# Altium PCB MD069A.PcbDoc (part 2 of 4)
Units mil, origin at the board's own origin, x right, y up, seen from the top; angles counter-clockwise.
Board outline 4569 x 3239 mil, 4 copper layers (Top Layer, Signal Layer 1, Signal Layer 2, Bottom Layer), stack 61.2 mil thick; 187 components, 103 nets, 560 pads, 220 vias.
Unrouted connection lines stored in the file: 7.
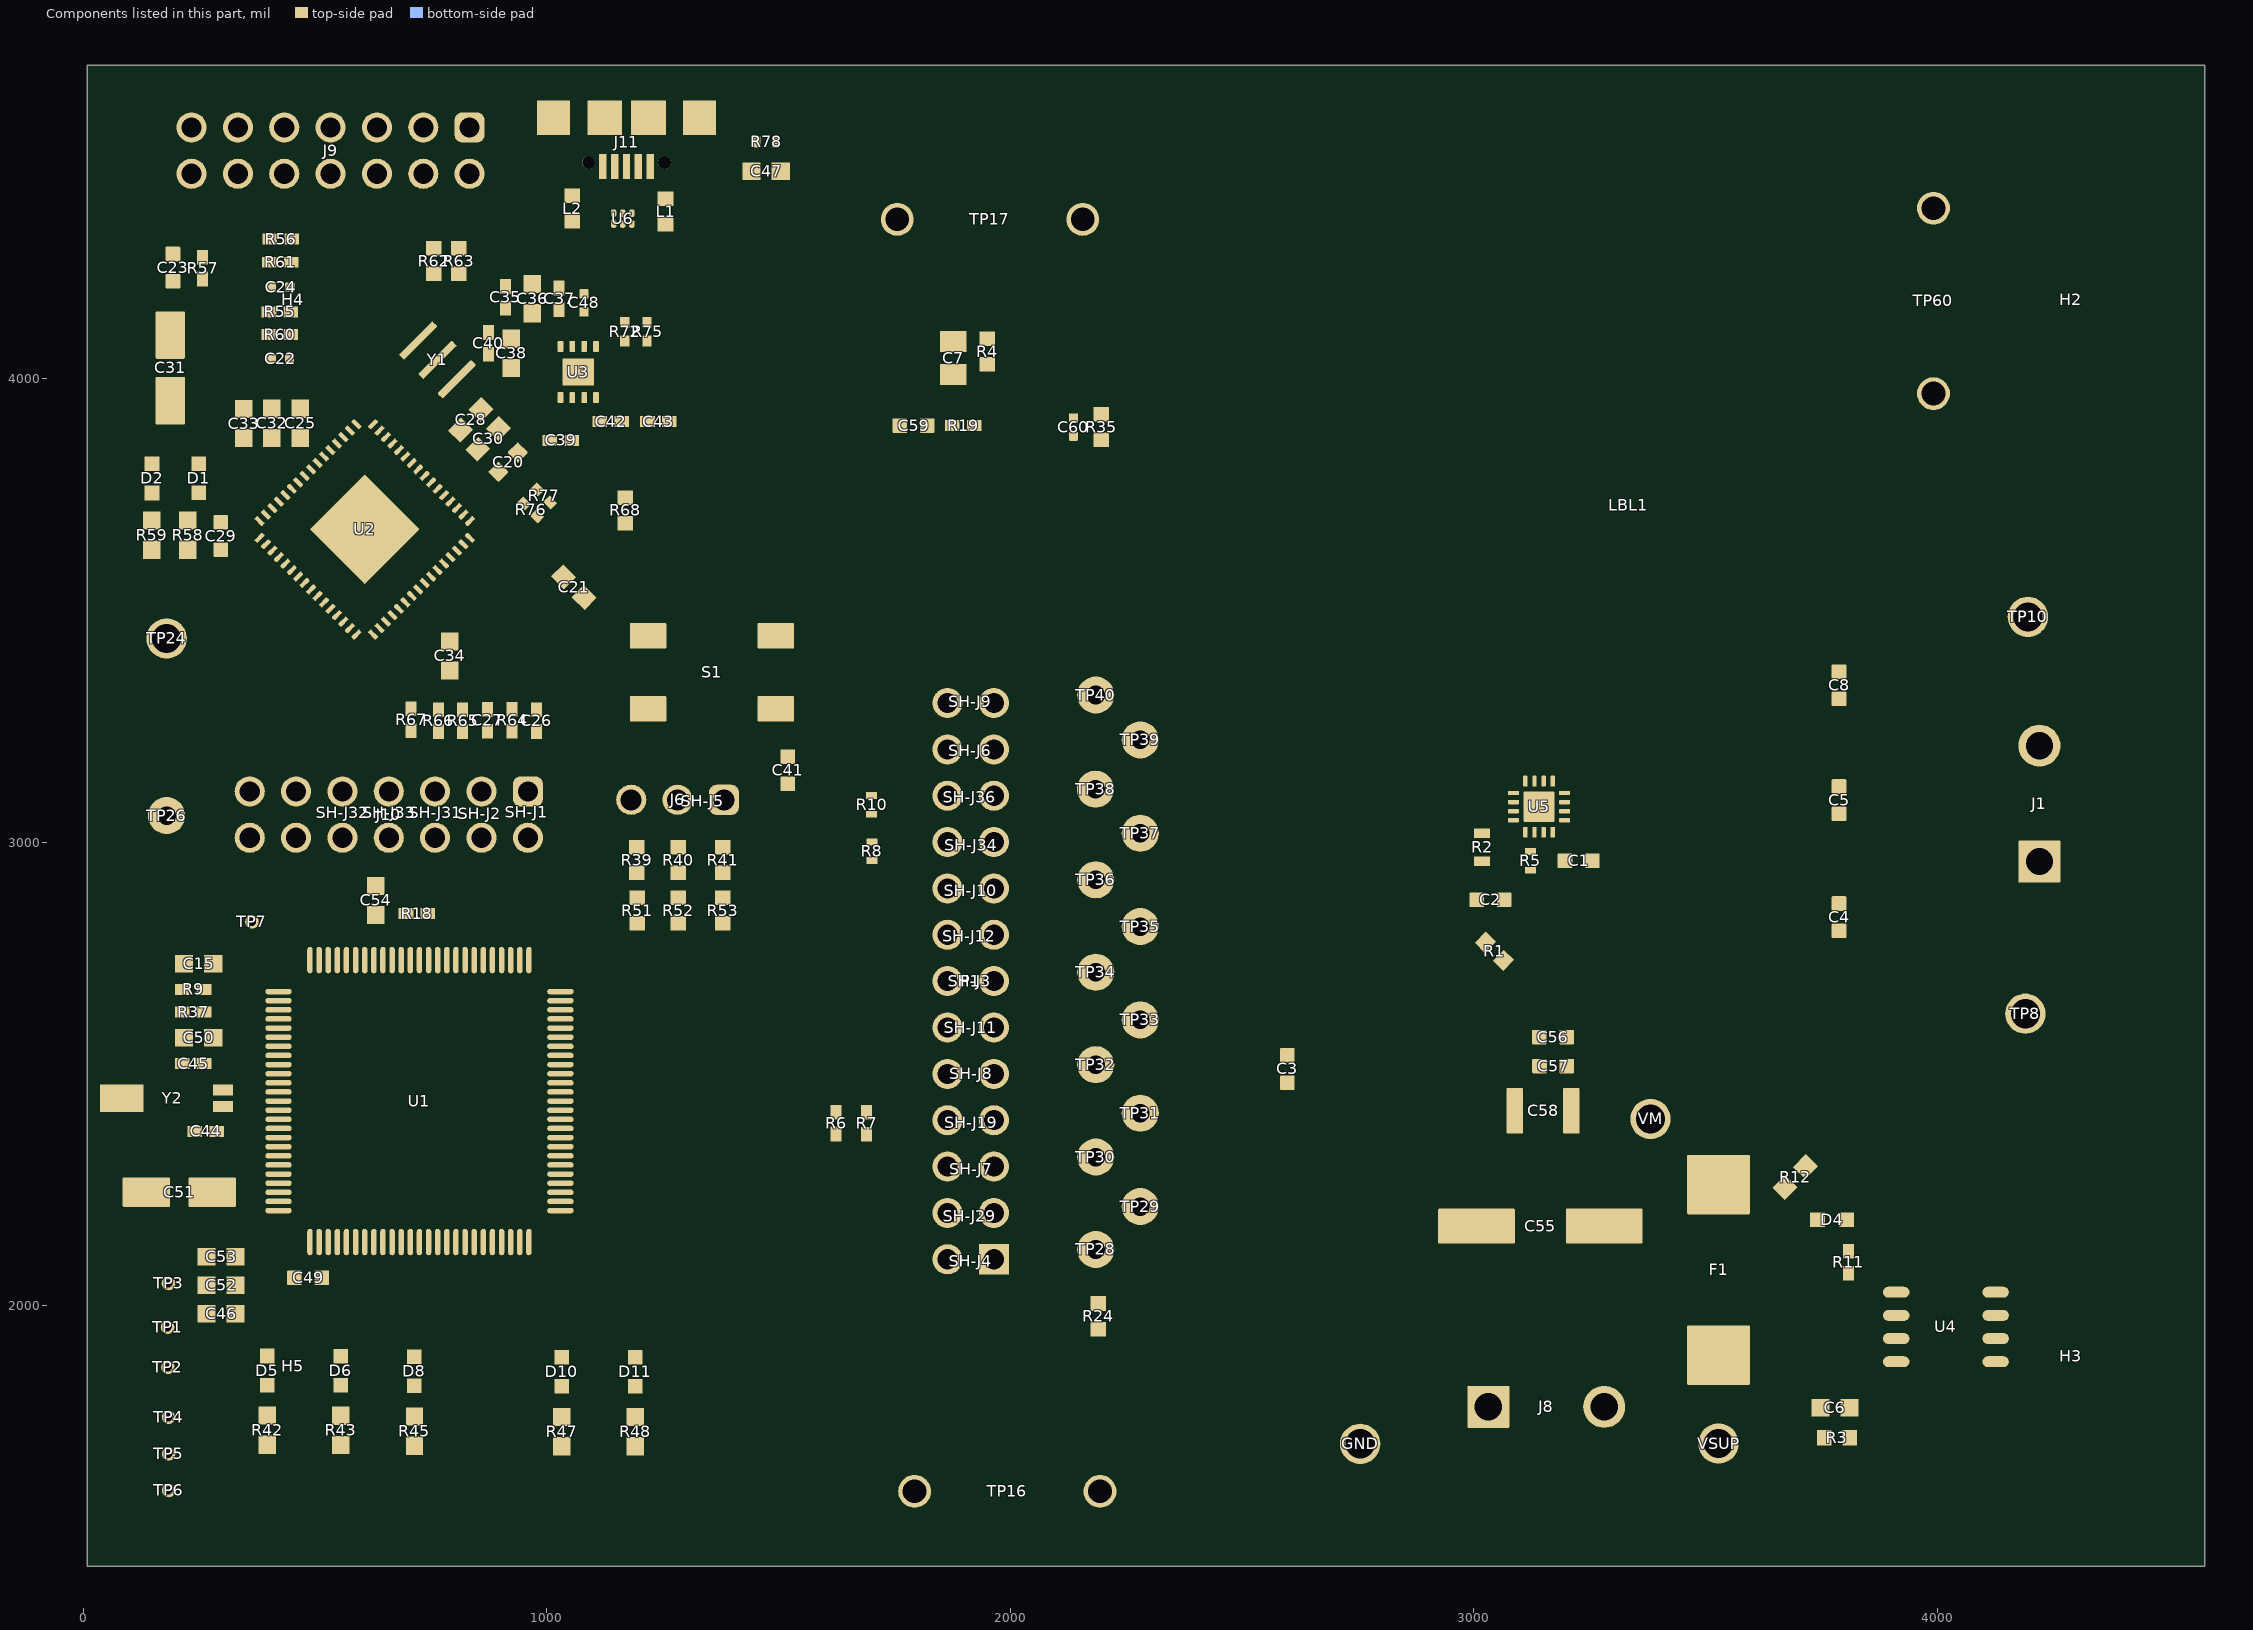
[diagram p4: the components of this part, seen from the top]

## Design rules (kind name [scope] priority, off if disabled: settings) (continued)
PolygonConnect PolygonConnect_4 [All vs IsNamedPolygon('TOP_LAYER_VM_P046')] p91: connectstyle=Direct reliefconductorwidth=10 reliefentries=4 polygonreliefangle="90 Angle" airgapwidth=10
PolygonConnect PolygonConnect_3 [All vs IsNamedPolygon('TOP_LAYER_GND_P036') Or  IsNamedPolygon('TOP_LAYER_OUT2_P040') Or  IsNamedPolygon('TOP_LAYER_OUT1_P038')] p92: connectstyle=Direct reliefconductorwidth=10 reliefentries=4 polygonreliefangle="90 Angle" airgapwidth=10
PolygonConnect PolygonConnect_2 [InNet('EZFET_VBUS') vs IsNamedPolygon('TOP_LAYER_EZFET_VBUS_P008')] p93: connectstyle=Direct reliefconductorwidth=10 reliefentries=4 polygonreliefangle="90 Angle" airgapwidth=10
PolygonConnect PolygonConnect_1 [InNetClass('Power-Net') vs IsNamedPolygon('TOP_LAYER_EZFET_USB_SHIELD_P201')] p94: connectstyle=Direct reliefconductorwidth=10 reliefentries=4 polygonreliefangle="90 Angle" airgapwidth=10
PolygonConnect [All] p95: connectstyle=Direct reliefconductorwidth=10 reliefentries=4 polygonreliefangle="90 Angle" airgapwidth=10
RoutingVias ThermalPadVias [IsVia and InAnyComponent] p1: holewidth=7.87 width=19.68 viastyle="Through Hole" minholewidth=7.87 minwidth=19.68 maxholewidth=12.99 maxwidth=23.62
RoutingVias [All] p2: holewidth=16 width=34 viastyle="Through Hole" minholewidth=7.87 minwidth=26 maxholewidth=40 maxwidth=65
SilkToBoardRegionClearance [Not ((IsComment or IsDesignator) And (Hide <> 'False')) and not InRegion(1000,500,4000,800)] p1:
SilkToSilkClearance SilkToSilkClearance_Pb-FreeLogo [(HasFootprint('Pb-Free_Overlay_Medium') OR HasFootprint('Pb-Free_Overlay_Small')) vs (HasFootprint('Pb-Free_Overlay_Medium') OR HasFootprint('Pb-Free_Overlay_Small'))] p1: silktosilkclearance=0
SilkToSilkClearance [All] p2: silktosilkclearance=3.94
SilkToSolderMaskClearance SilkToComponentPadClearance [(IsPad or IsFill or IsRegion) and InAnycomponent] p1: minsilkscreentomaskgap=5 clearancetoexposedcopper=TRUE
SilkToSolderMaskClearance "Silk to Solder Mask Opening" [All] p2: minsilkscreentomaskgap=3.94 clearancetoexposedcopper=FALSE
SolderMaskExpansion [All] p1: expansion=1.97 istentingtop=FALSE
UnRoutedNet [All] p1: checkbadconnections=TRUE
Width [All] p1: maxlimit=65 minlimit=4 preferedwidth=15 minimp=50.000000 maximp=50.000000 favimp=50.000000 checkconnectedcopper=TRUE
14 further rules are at their usual default settings.

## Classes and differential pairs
component class MD069A_Hardware: !PCB1 H2 H3 H4 H5 LBL1 Logo1 Logo2 Logo3 Logo4 LOGO5 ZZ1 ZZ2 ZZ3 ZZ4
component class MD069A: C1 C2 C3 C4 C5 C6 C7 C8 C15 C41 C44 C45 C46 C49 C50 C51 C52 C53 C54 C55 C56 C57 C58 C59 C60 D4 D5 D6 D8 D10 D11 F1 GND J1 J6 J8 P1 R1 R2 R3 R4 R5 R6 R7 R8 R9 R10 R11 R12 R18 R19 R24 R35 R37 R39 R40 R41 R42 R43 R45 R47 R48 R51 R52 R53 S1 SH-J1 SH-J2 SH-J3 SH-J4 SH-J5 SH-J6 SH-J7 SH-J8 SH-J9 SH-J10 SH-J11 SH-J12 SH-J19 SH-J36 TP1 TP2 TP3 TP4 TP5 TP6 TP7 TP8 TP10 TP16 TP17 TP24 TP26 TP28 TP29 TP30 TP31 TP32 TP33 TP34 TP35 TP36 TP37 TP38 TP39 TP40 TP60 U1 U4 U5 VM VSUP Y2
component class Shunt: SH-J1 SH-J2 SH-J3 SH-J4 SH-J5 SH-J6 SH-J7 SH-J8 SH-J9 SH-J10 SH-J11 SH-J12 SH-J19 SH-J29 SH-J31 SH-J32 SH-J33 SH-J34 SH-J36
net class Power-Net: EZFET_VBUS EZFET_VCC GND MCU_3V3
component class Header: J6 J9 J10
component class MD069A_ezFET: C20 C21 C22 C23 C24 C25 C26 C27 C28 C29 C30 C31 C32 C33 C34 C35 C36 C37 C38 C39 C40 C42 C43 C47 C48 D1 D2 J9 J10 J11 L1 L2 R55 R56 R57 R58 R59 R60 R61 R62 R63 R64 R65 R66 R67 R68 R72 R75 R76 R77 R78 SH-J29 SH-J31 SH-J32 SH-J33 SH-J34 U2 U3 U6 Y1
component class Logo: Logo2
component class AssemblyNote: ZZ1 ZZ2 ZZ3 ZZ4
component class Label: LBL1
differential pair USB_D: +USB_D_P -USB_D_N
differential pair EZFET_D: +EZFET_D_P -EZFET_D_N

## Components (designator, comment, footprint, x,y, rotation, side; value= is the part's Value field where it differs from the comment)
C1 "885012206120" FP-885012206120_0603-MFG 3225.89,2960.41 r180 top value=100nF
C2 "885012206120" FP-885012206120_0603-MFG 3035.54,2875.94 r0 top value=100nF
C3 "885012006085" FP-885012006085_0603-MFG 2597.56,2511.17 r90 top value=1nF
C4 "885012006085" FP-885012006085_0603-MFG 3787.61,2838.57 r90 top value=1nF
C5 "885012006085" FP-885012006085_0603-MFG 3787.61,3091.04 r270 top value=1nF
C6 "885012206095" 0603 3778.83,1780.3 r0 top value=0.1uF
C7 "885012107011" 0805_150 1876.75,4044.85 r270 top value=22uF
C8 "885012006085" FP-885012006085_0603-MFG 3787.61,3339.04 r270 top value=1nF
C15 "885012206095" 0603 248.63,2738.54 r180 top value=0.1uF
C20 "885012106012" FP-885012106012_0603-MFG 916.28,3820.21 r225 top value=4.7µF
C21 "885012206095" 0603 1058.3,3550.7 r315 top value=0.1uF
C22 "885012005058" FP-885012005058_0402-MFG 425.27,4043.12 r0 top value=33pF
C23 "885012006085" FP-885012006085_0603-MFG 193.39,4239.89 r90 top value=1nF
C24 "885012005058" FP-885012005058_0402-MFG 425.71,4197.93 r0 top value=33pF
C25 "885012206095" 0603 467.95,3904.1 r90 top value=0.1uF
C26 "885012005055" 0402 977.55,3262.77 r270 top value=10pF
C27 "885012005055" 0402 871.56,3263 r270 top value=10pF
C28 "885012206048" 0603 835.93,3911.48 r45 top value=0.22uF
C29 "885012106008" FP-885012106008_0603-MFG 296.85,3660.71 r270 top value=470nF
C30 "885012206048" 0603 873.13,3870.41 r45 top value=0.22uF
C31 "875105240001" FP-875105240001_SMT_CAP_4MM3_4MM3-MFG 187.54,4023.63 r270 top value=10µF
C32 "885012206095" 0603 406.51,3904.1 r90 top value=0.1uF
C33 "885012206095" 0603 346.36,3903.67 r90 top value=0.1uF
C34 "885012206095" 0603 790.72,3402.12 r90 top value=0.1uF
C35 "885012105012" 0402 910.39,4175.6 r90 top value=1uF
C36 "885012206095" 0603 968.11,4173.17 r90 top value=0.1uF
C37 "885012205031" 0402 1026.24,4172.43 r90 top value=0.01uF
C38 "885012106018" 0603 922.83,4055.06 r90 top value=2.2uF
C39 "885012205031" 0402 1029.71,3867.23 r0 top value=0.01uF
C40 "885012105012" 0402 873.88,4076.47 r90 top value=1uF
C41 "885012006085" FP-885012006085_0603-MFG 1519.79,3155.67 r270 top value=1nF
C42 "885012005055" 0402 1137.9,3907.66 r180 top value=10pF
C43 "885012005055" 0402 1240.69,3907.66 r0 top value=10pF
C44 "885012005055" 0402 263.9,2376.79 r0 top value=10pF
C45 "885012005055" 0402 236.65,2522.82 r180 top value=10pF
C46 "885012206095" 0603 297.02,1983.23 r0 top value=0.1uF
C47 "885012206048" 0603 1473,4448.03 r0 top value=0.22uF
C48 "885012205018" FP-885012205018_0402-MFG 1080,4164 r90 top value=100nF
C49 "885012106008" FP-885012106008_0603-MFG 484.94,2060.9 r0 top value=470nF
C50 "885012206095" 0603 248.63,2578.4 r180 top value=0.1uF
C51 "875105240001" FP-875105240001_SMT_CAP_4MM3_4MM3-MFG 206.98,2245.41 r0 top value=10µF
C52 "885012206095" 0603 297.02,2044.31 r180 top value=0.1uF
C53 "885012206095" 0603 297.02,2105.92 r180 top value=0.1uF
C54 "885012206095" 0603 630.92,2874.69 r270 top value=0.1uF
C55 "865060653010" WCAP-ASLL_800x1050 3143.27,2172.32 r180 top value=100uF
C56 "885012206120" FP-885012206120_0603-MFG 3170.41,2580.05 r0 top value=100nF
C57 "885012006085" FP-885012006085_0603-MFG 3170.93,2517.49 r0 top value=1nF
C58 "885012209069" FP-885012209069_1210-MFG 3149.12,2420.93 r0 top value=1µF
C59 "885012006085" FP-885012006085_0603-MFG 1791,3899 r0 top value=1nF
C60 "885012005080" FP-885012005080_0402-MFG 2136,3896 r270 top value=100pF
D1 "150060RS75000" WL-SMCW_RED 249.42,3785.56 r270 top value=Red
D2 "150060VS75000" WL-SMCW_GREEN 148.2,3785.34 r270 top value=Green
D4 "150060VS75000" WL-SMCW_GREEN 3772.65,2186.22 r180 top value=Green
D5 "150060VS75000" WL-SMCW_GREEN 396.79,1860.48 r90 top value=Green
D6 "150060VS75000" WL-SMCW_GREEN 555.36,1860 r90 top value=Green
D8 "150060VS75000" WL-SMCW_GREEN 714.26,1859 r90 top value=Green
D10 "150060YS75000" WL-SMCW_YELLOW 1032.04,1858 r90 top value=Yellow
D11 "150060SS75000" WL-SMCW_RED 1190.94,1858 r90 top value="Super Red"
F1 "0463030.ER" Fuse_0463 3527.57,2077.72 r90 top
GND "5011" Keystone5011 2754.6,1702.49 r270 top
H2 "SJ61A1" Bumpon_SJ61A1 4287,4171 r180 bottom
H3 "SJ61A1" Bumpon_SJ61A1 4287,1891.31 r180 bottom
H4 "SJ61A1" Bumpon_SJ61A1 452,4171 r180 bottom
H5 "SJ61A1" Bumpon_SJ61A1 452,1870 r180 bottom
J1 "691250610002" FP-691250610002_CONN_TERM_BLOCK2-MFG 4284.9,3071.9 r90 top
J6 "61300311121" WURTH_61300311121 1282,3091.91 r180 top
J8 "691250610002" FP-691250610002_CONN_TERM_BLOCK2-MFG 3144.18,1717.35 r0 top
J9 "61301421121" Wurth_61301421121 533.43,4492.4 r270 top
J10 "61301421121" Wurth_61301421121 659,3060.02 r270 top
J11 "629105136821" 629105136821 1171.82,4563.32 r180 top
L1 "742792621" 0603L 1255.92,4360.74 r270 top value="140 ohm"
L2 "742792621" 0603L 1054.9,4367.31 r270 top value="140 ohm"
LBL1 "THT-14-423-10" Label_650x200 3332.42,3727.31 r0 top
Logo1 "CE Mark" CE_Mark_5mm 2540.7,3556.79 r0 top
Logo2 "Texas Instruments" TI_Stacked_Overlay_Medium 3116.15,4366.68 r0 top
Logo3 "FCC disclaimer" FCC_disclaimer 1560.47,1632 r0 top
Logo4 "WEEE logo" WEEE_Minimum 2508.73,3972.39 r0 top
LOGO5 "CAUTION HOT SURFACE" IEC_HotSurface_Small 3521.09,3066.59 r0 top
P1 "61302621121" 61302621121 1914.3,2700.7 r90 top
R1 "RC0603JR-0710KL" 0603L 3043.95,2765.1 r315 top value=10k
R2 "ERJ-3EKF1501V" 0603S 3017.48,2989.55 r270 top value=1.50k
R3 "Resistor" 0603L 3783.18,1715.13 r180 top value=0
R4 "Resistor" 0603L 1950,4059 r90 top value=0
R5 "RC0402JR-070RL" 0402S 3121.71,2959.91 r90 top value=0
R6 "CRCW04022K21FKED" 0402 1624.16,2394.62 r90 top value=2.21k
R7 "CRCW04022K21FKED" 0402 1689.93,2394.36 r90 top value=2.21k
R8 "RC0402JR-070RL" 0402S 1701.01,2980.93 r90 top value=0
R9 "CRCW040210R0FKED" 0402 236.65,2683.03 r180 top value=10.0
R10 "RC0402JR-070RL" 0402S 1700.67,3080.69 r90 top value=0
R11 "CRCW0402680RJNED" 0402 3807.56,2094.38 r90 top value=680
R12 "RG1608P-3012-B-T5" 0603 3693.21,2278.11 r225 top value=30.1k
R18 "CRCW040247K0JNED" 0402 719.67,2846.49 r0 top value=47k
R19 "CRCW040247K0JNED" 0402 1898.54,3899.14 r0 top value=47k
R24 "RC0603JR-0710KL" 0603L 2189.37,1977.63 r90 top value=10k
R35 "CRCW06034K99FKEA" 0603L 2196,3896 r270 top value=4.99k
R37 "CRCW040210R0FKED" 0402 236.65,2633.71 r0 top value=10.0
R39 "RC0603JR-0710KL" 0603L 1194.18,2961.73 r270 top value=10k
R40 "RC0603JR-0710KL" 0603L 1283.18,2961.73 r270 top value=10k
R41 "RC0603JR-0710KL" 0603L 1379.34,2961.73 r270 top value=10k
R42 "RC0603JR-07560RL" 0603 396.5,1732.21 r90 top value=560
R43 "CRCW0603330RJNEA" 0603 555.4,1731.74 r90 top value=330
R45 "CRCW0603330RJNEA" 0603 714.29,1729.74 r90 top value=330
R47 "CRCW0603330RJNEA" 0603 1032.08,1728.74 r90 top value=330
R48 "CRCW0603330RJNEA" 0603 1190.97,1728.74 r90 top value=330
R51 "RC0603JR-0710KL" 0603L 1194.54,2852.73 r270 top value=10k
R52 "RC0603JR-0710KL" 0603L 1283.61,2852.73 r270 top value=10k
R53 "RC0603JR-0710KL" 0603L 1379.69,2852.73 r270 top value=10k
R55 "RC0402FR-07220KL" 0402 424.06,4144.57 r180 top value=220k
R56 "CRCW0402240KFKED" 0402 425.71,4301.28 r180 top value=240k
R57 "CRCW040247K0JNED" 0402 257.39,4239.11 r270 top value=47k
R58 "RC0603JR-07470RL" 0603 225.05,3662.98 r90 top value=470
R59 "RC0603JR-07560RL" 0603 147.47,3662.94 r90 top value=560
R60 "RC0402FR-07220KL" 0402 423.82,4095.42 r0 top value=220k
R61 "CRCW0402150KFKED" 0402 425.32,4251.56 r0 top value=150k
R62 "Resistor" 0603L 756.08,4254.24 r270 top value=0
R63 "Resistor" 0603L 809.84,4253.99 r270 top value=0
R64 "CRCW040210R0FKED" 0402 924.87,3263.29 r270 top value=10.0
R65 "CRCW040210R0FKED" 0402 818.39,3262.44 r270 top value=10.0
R66 "CRCW040210R0FKED" 0402 765.89,3262.8 r270 top value=10.0
R67 "CRCW040210R0FKED" 0402 706.9,3264.38 r270 top value=10.0
R68 "Resistor" 0603L 1169.5,3716.36 r90 top value=0
R72 "CRCW040227R0JNED" 0402L 1167.94,4101.57 r270 top value=27
R75 "CRCW040227R0JNED" 0402L 1216.37,4101.57 r270 top value=27
R76 "CRCW04021K40FKED" 0402L 964.89,3717.33 r315 top value=1.40k
R77 "CRCW04021M00JNED" 0402L 993.35,3747.35 r135 top value=1.0Meg
R78 "CRCW040233K0JNED" 0402S 1473,4511 r180 top value=33k
S1 "430481025816" FP-430481025816_SMT_SW_6MM2_6MM2-MFG 1356,3367 r180 top
SH-J1 "60900213421" Wurth_60900213421 956.09,3064.66 r90 top
SH-J2 "60900213421" Wurth_60900213421 855.52,3062.26 r90 top
SH-J3 "60900213421" Wurth_60900213421 1912.17,2700.94 r180 top
SH-J4 "60900213421" Wurth_60900213421 1914.34,2096.07 r180 top
SH-J5 "60900213421" Wurth_60900213421 1336.05,3088.57 r180 top
SH-J6 "60900213421" Wurth_60900213421 1913.63,3197.29 r180 top
SH-J7 "60900213421" Wurth_60900213421 1915.5,2294.66 r180 top
SH-J8 "60900213421" Wurth_60900213421 1915.5,2500.47 r180 top
SH-J9 "60900213421" Wurth_60900213421 1912.93,3303.11 r180 top
SH-J10 "60900213421" Wurth_60900213421 1914.83,2895.42 r180 top
SH-J11 "60900213421" Wurth_60900213421 1913.95,2600.07 r180 top
SH-J12 "60900213421" Wurth_60900213421 1911.43,2797.73 r180 top
SH-J19 "60900213421" Wurth_60900213421 1915.5,2395.23 r180 top
SH-J29 "60900213421" Wurth_60900213421 1912.26,2193.54 r180 top
SH-J31 "60900213421" Wurth_60900213421 760,3064 r90 top
SH-J32 "60900213421" Wurth_60900213421 560,3064 r90 top
SH-J33 "60900213421" Wurth_60900213421 660,3064 r90 top
SH-J34 "60900213421" Wurth_60900213421 1915.02,2993.99 r180 top
SH-J36 "60900213421" Wurth_60900213421 1912.23,3097.03 r180 top
TP1 "TP_H0.45P0.75" TP_H045P075 181.74,1954.01 r0 top
TP2 "TP_H0.45P0.75" TP_H045P075 182.41,1867.43 r90 top
TP3 "TP_H0.45P0.75" TP_H045P075 183.74,2048.59 r0 top
TP4 "TP_H0.45P0.75" TP_H045P075 184,1760 r0 top
TP5 "TP_H0.45P0.75" TP_H045P075 184,1681 r0 top
TP6 "TP_H0.45P0.75" TP_H045P075 184,1602 r90 top
TP7 "TP_H0.45P0.75" TP_H045P075 363.7,2828.57 r90 top
TP8 "5012" Keystone5012 4189.57,2630.36 r90 top
TP10 "5012" Keystone5012 4195.05,3486.48 r90 top
TP16 "Jumper_2p" Harwin_D3082-05 1993.22,1599.99 r180 top
TP17 "Jumper_2p" Harwin_D3082-05 1955.92,4344.03 r0 top
TP24 "5011" Keystone5011 179.7,3440 r0 top
TP26 "5003" Keystone5003 179.7,3057.87 r0 top
TP28 "5002" Keystone5002 2184.18,2121.77 r0 top
TP29 "5002" Keystone5002 2280.18,2214.47 r0 top
TP30 "5002" Keystone5002 2184.18,2321.14 r0 top
TP31 "5002" Keystone5002 2280.18,2415.79 r0 top
TP32 "5002" Keystone5002 2184.18,2520.5 r0 top
TP33 "5002" Keystone5002 2280.18,2617.1 r180 top
TP34 "5002" Keystone5002 2184.18,2719.86 r180 top
TP35 "5002" Keystone5002 2280.18,2818.42 r180 top
TP36 "5002" Keystone5002 2184.18,2919.23 r180 top
TP37 "5002" Keystone5002 2280.18,3019.73 r180 top
TP38 "5002" Keystone5002 2183.57,3114.89 r180 top
TP39 "5002" Keystone5002 2280.18,3221.05 r180 top
TP40 "5002" Keystone5002 2184.18,3317.95 r180 top
TP60 "Jumper_2p" Harwin_D3082-05 3991.31,4168.2 r270 top
U1 "MSP430F5338IPZ" PZT0100A_N 725.16,2442 r0 top
U2 "MSP430F5528IRGCT" RGC0064B 606.92,3675.21 r315 top
U3 "TPS73533DRBR" DRB0008A 1067.69,4014.77 r90 top
U4 "LM9036M-3.3/NOPB" D0008A_N 4018.2,1954.66 r180 top
U5 "DRV8214RTER" RTE0016C-MFG 3140.46,3077.05 r90 top
U6 "TPD2E001DRYR" DRY0006A 1163.72,4345.58 r90 top
VM "5010" Keystone5010 3380.98,2403.35 r270 top
VSUP "5010" Keystone5010 3527.57,1703.13 r270 top
Y1 "CSTNR4M00GH5L000R0" MuRata_CSTNR 764.02,4040.94 r135 top
Y2 "MS3V-T1R 32.768KHZ +/-20PPM 12.5PF" XTAL_MS3V-T1R 192,2448 r180 top
ZZ1 "These assemblies are ESD sensitive, ESD precautions shall be observed." AssemblyNote 1277,977 r0 top
ZZ2 "These assemblies must be clean and free from flux and all contaminants. Use of no clean flux is not acceptable." AssemblyNote 1268,1071 r0 top
ZZ3 "These assemblies must comply with workmanship standards IPC-A-610 Class 2, unless otherwise specified." AssemblyNote 1268,874 r0 top
ZZ4 "This Assembly Note is for PCB labels only" AssemblyNoteLabel 1263,775 r0 top

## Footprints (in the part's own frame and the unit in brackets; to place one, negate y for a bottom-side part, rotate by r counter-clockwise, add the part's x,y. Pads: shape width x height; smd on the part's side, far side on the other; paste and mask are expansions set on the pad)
0402 [mm] "0402 from SM-752 data"
  rect 0.8x0.6 smd: 1(-0.6,0) 2(0.6,0)
  silkscreen extent -1.22,-0.52 1.22,0.52, body extent -0.55,-0.3 0.55,0.3, height 0.6
0402L [mm] "0402 from SM-752 data"
  rect 0.6x0.5 smd: 1(-0.5,0) 2(0.5,0)
  body extent -0.55,-0.3 0.55,0.3, height 0.6
0402S [mil] "Based on C0402S footprint from PADS legacy"
  rect 15x24 smd: 1(-20,0) 2(20,0)
  body extent -22,-12 22,12, height 24
0603 [mm] "0603 from SM-752 data"
  rect 1x0.95 smd: 1(-0.8,0) 2(0.8,0)
  silkscreen extent -1.52,-0.69 1.52,0.69, body extent -0.87,-0.47 0.87,0.47, height 1
0603L [mm] "0603 from SM-752 data"
  rect 0.8x0.85 smd: 1(-0.7,0) 2(0.7,0)
  silkscreen extent -0.07,-0.33 0.07,0.33, body extent -0.87,-0.47 0.87,0.47, height 1
0603S [mil]
  rect 20x35 smd: 1(-30,0) 2(30,0)
  body extent -34,-19 34,19, height 39
0805_150 [mm] "0805 / 1.5 mm height"
  rect 1.15x1.45 smd: 1(-0.9,0) 2(0.9,0)
  silkscreen extent -0.1,-0.8 0.1,0.8, body extent -1.1,-0.72 1.1,0.72, height 1.5
61302621121 [mm] "Pin Header, pitch 2.54 mm, THT, Vertical, dual row, 26p"
  rect 1.65x1.65 hole 1.1: 1(-15.24,-1.27)
  round 1.65 hole 1.1: 2(-15.24,1.27) 3(-12.7,-1.27) 4(-12.7,1.27) 5(-10.16,-1.27) 6(-10.16,1.27) 7(-7.62,-1.27) 8(-7.62,1.27) 9(-5.08,-1.27) 10(-5.08,1.27) 11(-2.54,-1.27) 12(-2.54,1.27) 13(0,-1.27) 14(0,1.27) 15(2.54,-1.27) 16(2.54,1.27) 17(5.08,-1.27) 18(5.08,1.27) 19(7.62,-1.27) 20(7.62,1.27) 21(10.16,-1.27) 22(10.16,1.27) 23(12.7,-1.27) 24(12.7,1.27) 25(15.24,-1.27) 26(15.24,1.27)
  silkscreen extent -16.66,-2.62 16.66,2.62, body extent -16.51,-2.54 16.51,2.54, height 8.59
629105136821 [mm] "Micro USB 2.0 SMT Type B Horizontal 5 Contacts"
  rect 0.4x1.35 smd: 1(-1.3,2.675) 2(-0.65,2.675) 3(0,2.675) 4(0.65,2.675) 5(1.3,2.675)
  round 0.7 hole 0.7 unplated: MH1(-2.075,2.45) MH2(2.075,2.45)
  rect 1.8x1.9 smd: Shell(-4,0) Shell(4,0)
  rect 1.9x1.9 smd: Shell(-1.2,0) Shell(1.2,0)
  silkscreen extent -3.7,1.25 3.7,2.85, body extent -4,-2.73 4,3.17, height 2.69
AssemblyNote [mil] "Assembly Note"
AssemblyNoteLabel [mil] "Assembly Note for PCB Labels"
Bumpon_SJ61A1 [mil] "3M Cylindrical Bumpon black"
  round 1 on Mech4: 0(0,0)
  silkscreen extent -156,-156 156,156, body extent -156,-156 156,156, height 201
CE_Mark_5mm [mil] "Minimum text height for CE Mark"
  silkscreen extent -138,-98 138,98
D0008A_N [mm] "SOIC, 8-Leads, Body 4.9x3.9mm, Pitch 1.27mm, IPC Medium Density"
  oval 1.45x0.6 smd: 1(-2.725,1.905) 2(-2.725,0.635) 3(-2.725,-0.635) 4(-2.725,-1.905) 5(2.725,-1.905) 6(2.725,-0.635) 7(2.725,0.635) 8(2.725,1.905)
  silkscreen extent -3.3,-2.5 0.9,2.5, body extent -3,-2.45 3,2.45, height 1.63
DRB0008A [mm] "VSON-8"
  rrect32% 0.6x0.31 smd: 1(-1.4,0.975) 2(-1.4,0.325) 3(-1.4,-0.325) 4(-1.4,-0.975) 5(1.4,-0.975) 6(1.4,-0.325) 7(1.4,0.325) 8(1.4,0.975)
  rrect7% 1.5x1.75 smd paste-0.75: 9(0,0)
  Top Layer region: -0.7,-0.875 -0.49,-0.875 -0.471,-0.879 -0.455,-0.89 -0.444,-0.906 -0.44,-0.925 -0.44,-0.925 -0.44,-1.65 -0.436,-1.669 -0.425,-1.685 -0.409,-1.696 -0.39,-1.7 -0.39,-1.7 -0.26,-1.7 -0.241,-1.696 -0.225,-1.685 -0.214,-1.669 -0.21,-1.65 -0.21,-1.65 -0.21,-0.925 -0.206,-0.906 -0.195,-0.89 -0.179,-0.879 -0.16,-0.875 -0.16,-0.875 0.16,-0.875 0.179,-0.879 0.195,-0.89 0.206,-0.906 0.21,-0.925 0.21,-0.925 0.21,-1.65 0.21,-1.65 0.214,-1.669 0.225,-1.685 0.241,-1.696 0.26,-1.7 0.26,-1.7 0.39,-1.7 0.409,-1.696 0.425,-1.685 0.436,-1.669 0.44,-1.65 0.44,-1.65 0.44,-0.925 0.444,-0.906 0.455,-0.89 0.471,-0.879 0.49,-0.875 0.49,-0.875 0.7,-0.875 0.719,-0.871 0.735,-0.86 0.746,-0.844 0.75,-0.825 0.75,-0.825 0.75,0.825 0.746,0.844 0.735,0.86 0.719,0.871 0.7,0.875 0.7,0.875 0.49,0.875 0.471,0.879 0.455,0.89 0.444,0.906 0.44,0.925 0.44,0.925 0.44,1.65 0.436,1.669 0.425,1.685 0.409,1.696 0.39,1.7 0.39,1.7 0.26,1.7 0.241,1.696 0.225,1.685 0.214,1.669 0.21,1.65 0.21,1.65 0.21,1.65 0.21,0.925 0.206,0.906 0.195,0.89 0.179,0.879 0.16,0.875 0.16,0.875 -0.16,0.875 -0.179,0.879 -0.195,0.89 -0.206,0.906 -0.21,0.925 -0.21,0.925 -0.21,1.65 -0.214,1.669 -0.225,1.685 -0.241,1.696 -0.26,1.7 -0.26,1.7 -0.39,1.7 -0.409,1.696 -0.425,1.685 -0.436,1.669 -0.44,1.65 -0.44,1.65 -0.44,0.925 -0.444,0.906 -0.455,0.89 -0.471,0.879 -0.49,0.875 -0.49,0.875 -0.7,0.875 -0.719,0.871 -0.735,0.86 -0.746,0.844 -0.75,0.825 -0.75,0.825 -0.75,-0.825 -0.746,-0.844 -0.735,-0.86 -0.719,-0.871 -0.7,-0.875
  silkscreen extent -1.73,-1.73 1.73,1.73, body extent -1.5,-1.5 1.5,1.5, height 0.77
DRY0006A [mm] "USON-6"
  rrect67% 0.45x0.3 smd paste-0.05 mask-0.05: 1(-0.275,0.5)
  rrect67% 0.4x0.3 smd paste-0.05 mask-0.05: 2(-0.3,0) 3(-0.3,-0.5) 4(0.3,-0.5) 5(0.3,0) 6(0.3,0.5)
  body extent -0.5,-0.72 0.5,0.73, height 0.58
FCC_disclaimer [mil]
FP-430481025816_SMT_SW_6MM2_6MM2-MFG [mm]
  rrect7% 2x1.4 smd paste+0 mask+0: 1(-3.5,2) 2(3.5,2) 3(-3.5,-2) 4(3.5,-2)
  silkscreen extent -5.18,-3.2 3.2,3.2, body extent -4.6,-3.3 4.6,3.3, height 0.25
FP-691250610002_CONN_TERM_BLOCK2-MFG [mm]
  rrect4% 2.3x2.3 hole 1.5 paste-1000 mask+0: 1(-2.875,1.65)
  round 2.3 hole 1.5 paste-1000 mask+0: 2(3.475,1.65)
  silkscreen extent -7.52,-6.3 6.85,6.3, body extent -6.95,-6.4 6.95,6.4, height 0.25
FP-875105240001_SMT_CAP_4MM3_4MM3-MFG [mm]
  rrect6% 2.6x1.6 smd paste+0 mask+0: 1(-1.8,0) 2(1.8,0)
  silkscreen extent -3.67,-2.25 2.25,2.25, body extent -3.35,-2.5 3.35,2.5, height 0.25
FP-885012005058_0402-MFG [mm]
  rrect20% 0.5x0.5 smd paste+0 mask+0: 1(-0.5,0) 2(0.5,0)
  silkscreen extent -0.53,-0.63 0.53,0.63, body extent -0.85,-0.38 0.85,0.38, height 0.25
FP-885012005080_0402-MFG [mm]
  rrect20% 0.5x0.5 smd paste+0 mask+0: 1(-0.5,0) 2(0.5,0)
  silkscreen extent -0.53,-0.63 0.53,0.63, body extent -0.85,-0.38 0.85,0.38, height 0.25
FP-885012006085_0603-MFG [mm]
  rrect13% 0.8x0.8 smd paste+0 mask+0: 1(-0.75,0) 2(0.75,0)
  silkscreen extent -0.85,-0.77 0.85,0.77, body extent -1.25,-0.55 1.25,0.55, height 0.25
FP-885012106008_0603-MFG [mm]
  rrect13% 0.8x0.8 smd paste+0 mask+0: 1(-0.75,0) 2(0.75,0)
  silkscreen extent -0.85,-0.77 0.85,0.77, body extent -1.25,-0.55 1.25,0.55, height 0.25
FP-885012106012_0603-MFG [mm]
  rrect13% 0.8x0.8 smd paste+0 mask+0: 1(-0.75,0) 2(0.75,0)
  silkscreen extent -0.85,-0.77 0.85,0.77, body extent -1.25,-0.55 1.25,0.55, height 0.25
FP-885012205018_0402-MFG [mm]
  rrect20% 0.5x0.5 smd paste+0 mask+0: 1(-0.5,0) 2(0.5,0)
  silkscreen extent -0.5,-0.63 0.5,0.63, body extent -0.85,-0.38 0.85,0.38, height 0.25
FP-885012206120_0603-MFG [mm]
  rrect13% 0.8x0.8 smd paste+0 mask+0: 1(-0.75,0) 2(0.75,0)
  silkscreen extent -0.85,-0.77 0.85,0.77, body extent -0.8,-0.4 0.8,0.4, height 0.87
FP-885012209069_1210-MFG [mm]
  rrect11% 0.9x2.5 smd paste+0 mask+0: 1(-1.55,0) 2(1.55,0)
  silkscreen extent -0.72,-1.4 0.72,1.4, body extent -2.1,-1.5 2.1,1.5, height 0.25
Fuse_0463 [mm] "SMD, 2-Leads, Body 10.1x3.12mm"
  rrect3% 3.25x3.43 smd: 1(-4.675,0) 2(4.675,0)
  silkscreen extent -2.6,-1.5 2.6,1.5, body extent -5.05,-1.56 5.05,1.56, height 3.12
Harwin_D3082-05 [mm] "Shorting Plug, 10.16mm spacing, TH"
  round 1.8 hole 1.3: 1(-5.08,0) 2(5.08,0)
  silkscreen extent -3.9,-0.53 3.9,0.53, body extent -5.6,-0.52 5.61,0.52, height 6.63
IEC_HotSurface_Small [mil]
  silkscreen extent -107,-93 107,92
Keystone5002 [mil] "For Keystone 500x miniature loop terminals"
  round 80 hole 40: 1(0,0)
  silkscreen extent -52,-52 52,52, body extent -49,-49 49,49, height 182
Keystone5003 [mil] "For Keystone 500x miniature loop terminals"
  round 80 hole 40: 1(0,0)
  silkscreen extent -52,-52 52,52, body extent -49,-49 49,49, height 182
Keystone5010 [mil] "Keystone Multipurpose loops"
  round 87 hole 63: 1(0,0)
  silkscreen extent -70,-70 70,70, body extent -63,-63 63,62, height 319
Keystone5011 [mil] "Keystone Multipurpose loops"
  round 87 hole 63: 1(0,0)
  silkscreen extent -70,-70 70,70, body extent -63,-63 63,62, height 319
Keystone5012 [mil] "Keystone Multipurpose loops"
  round 87 hole 63: 1(0,0)
  silkscreen extent -70,-70 70,70, body extent -63,-63 63,62, height 319
Label_650x200 [mil] "Thermal Transfer Label"
  round 1 on Mech13: 0(0,0)
  silkscreen extent -325,-100 325,100, body extent -325,-100 325,100, height 1
MuRata_CSTNR [mm] "SMD, 3-Leads, Body 4.5x2mm, Pitch 1.5mm"
  rrect25% 0.4x2.6 smd: 1(-1.5,0) 2(0,0) 3(1.5,0)
  body extent -2.3,-1.05 2.3,1.05, height 1.2
PZT0100A_N [mm] "QFP, 100-Leads, Body 14x14mm, Pitch 0.50mm, IPC Medium Density"
  oval 1.45x0.3 smd: 1(-7.725,6) 2(-7.725,5.5) 3(-7.725,5) 4(-7.725,4.5) 5(-7.725,4) 6(-7.725,3.5) 7(-7.725,3) 8(-7.725,2.5) 9(-7.725,2) 10(-7.725,1.5) 11(-7.725,1) 12(-7.725,0.5) 13(-7.725,0) 14(-7.725,-0.5) 15(-7.725,-1) 16(-7.725,-1.5) 17(-7.725,-2) 18(-7.725,-2.5) 19(-7.725,-3) 20(-7.725,-3.5) 21(-7.725,-4) 22(-7.725,-4.5) 23(-7.725,-5) 24(-7.725,-5.5) 25(-7.725,-6) 51(7.725,-6) 52(7.725,-5.5) 53(7.725,-5) 54(7.725,-4.5) 55(7.725,-4) 56(7.725,-3.5) 57(7.725,-3) 58(7.725,-2.5) 59(7.725,-2) 60(7.725,-1.5) 61(7.725,-1) 62(7.725,-0.5) 63(7.725,0) 64(7.725,0.5) 65(7.725,1) 66(7.725,1.5) 67(7.725,2) 68(7.725,2.5) 69(7.725,3) 70(7.725,3.5) 71(7.725,4) 72(7.725,4.5) 73(7.725,5) 74(7.725,5.5) 75(7.725,6)
  oval 0.3x1.45 smd: 26(-6,-7.725) 27(-5.5,-7.725) 28(-5,-7.725) 29(-4.5,-7.725) 30(-4,-7.725) 31(-3.5,-7.725) 32(-3,-7.725) 33(-2.5,-7.725) 34(-2,-7.725) 35(-1.5,-7.725) 36(-1,-7.725) 37(-0.5,-7.725) 38(0,-7.725) 39(0.5,-7.725) 40(1,-7.725) 41(1.5,-7.725) 42(2,-7.725) 43(2.5,-7.725) 44(3,-7.725) 45(3.5,-7.725) 46(4,-7.725) 47(4.5,-7.725) 48(5,-7.725) 49(5.5,-7.725) 50(6,-7.725) 76(6,7.725) 77(5.5,7.725) 78(5,7.725) 79(4.5,7.725) 80(4,7.725) 81(3.5,7.725) 82(3,7.725) 83(2.5,7.725) 84(2,7.725) 85(1.5,7.725) 86(1,7.725) 87(0.5,7.725) 88(0,7.725) 89(-0.5,7.725) 90(-1,7.725) 91(-1.5,7.725) 92(-2,7.725) 93(-2.5,7.725) 94(-3,7.725) 95(-3.5,7.725) 96(-4,7.725) 97(-4.5,7.725) 98(-5,7.725) 99(-5.5,7.725) 100(-6,7.725)
  silkscreen extent -8.1,-8.2 8.1,8.2, body extent -8.01,-8.01 8.01,8.01, height 1.6
RGC0064B [mm] "VQFN-64"
  rrect42% 0.6x0.24 smd mask+0.07: 1(-4.4,3.75) 2(-4.4,3.25) 3(-4.4,2.75) 4(-4.4,2.25) 5(-4.4,1.75) 6(-4.4,1.25) 7(-4.4,0.75) 8(-4.4,0.25) 9(-4.4,-0.25) 10(-4.4,-0.75) 11(-4.4,-1.25) 12(-4.4,-1.75) 13(-4.4,-2.25) 14(-4.4,-2.75) 15(-4.4,-3.25) 16(-4.4,-3.75) 33(4.4,-3.75) 34(4.4,-3.25) 35(4.4,-2.75) 36(4.4,-2.25) 37(4.4,-1.75) 38(4.4,-1.25) 39(4.4,-0.75) 40(4.4,-0.25) 41(4.4,0.25) 42(4.4,0.75) 43(4.4,1.25) 44(4.4,1.75) 45(4.4,2.25) 46(4.4,2.75) 47(4.4,3.25) 48(4.4,3.75)
  rrect42% 0.24x0.6 smd mask+0.07: 17(-3.75,-4.4) 18(-3.25,-4.4) 19(-2.75,-4.4) 20(-2.25,-4.4) 21(-1.75,-4.4) 22(-1.25,-4.4) 23(-0.75,-4.4) 24(-0.25,-4.4) 25(0.25,-4.4) 26(0.75,-4.4) 27(1.25,-4.4) 28(1.75,-4.4) 29(2.25,-4.4) 30(2.75,-4.4) 31(3.25,-4.4) 32(3.75,-4.4) 49(3.75,4.4) 50(3.25,4.4) 51(2.75,4.4) 52(2.25,4.4) 53(1.75,4.4) 54(1.25,4.4) 55(0.75,4.4) 56(0.25,4.4) 57(-0.25,4.4) 58(-0.75,4.4) 59(-1.25,4.4) 60(-1.75,4.4) 61(-2.25,4.4) 62(-2.75,4.4) 63(-3.25,4.4) 64(-3.75,4.4)
  rrect2% 4.25x4.25 smd paste-2.112: 65(0,0)
  body extent -4.5,-4.5 4.5,4.5, height 1
RTE0016C-MFG [mm]
  rrect42% 0.6x0.24 smd paste+0 mask+0: 1(-1.4,0.75) 2(-1.4,0.25) 3(-1.4,-0.25) 4(-1.4,-0.75) 9(1.4,-0.75) 10(1.4,-0.25) 11(1.4,0.25) 12(1.4,0.75)
  rrect42% 0.24x0.6 smd paste+0 mask+0: 5(-0.75,-1.4) 6(-0.25,-1.4) 7(0.25,-1.4) 8(0.75,-1.4) 13(0.75,1.4) 14(0.25,1.4) 15(-0.25,1.4) 16(-0.75,1.4)
  rrect6% 1.68x1.68 smd paste-1000 mask+0: 17(0,0)
  silkscreen extent -2.32,-1.55 1.55,1.55, body extent -1.8,-1.8 1.8,1.8, height 0.25
TI_Stacked_Overlay_Medium [mil]
  silkscreen extent -576,-136 576,134
TP_H045P075 [mm] "TP_H0.45P0.75"
  round 0.75 hole 0.45: 1(0,0)
WCAP-ASLL_800x1050 [mm] "SMD, 2-Leads, Dia 8mm"
  rrect5% 4.2x1.9 smd: 1(-3.5,0) 2(3.5,0)
  body extent -4.3,-4.25 4.3,4.25, height 10.51
WEEE_Minimum [mil] "WEEElie bin"
  silkscreen extent -95,-172 99,104
WL-SMCW_GREEN [mm] "WURTH"
  rect 0.8x0.8 smd: 1(-0.8,0) 2(0.8,0)
  silkscreen extent -1.9,-0.8 1.2,0.8, body extent -0.85,-0.45 0.85,0.45, height 0.8
WL-SMCW_RED [mm] "WURTH"
  rect 0.8x0.8 smd: 1(-0.8,0) 2(0.8,0)
  silkscreen extent -1.9,-0.8 1.2,0.8, body extent -0.85,-0.45 0.85,0.45, height 0.8
WL-SMCW_YELLOW [mm] "WURTH"
  rect 0.8x0.8 smd: 1(-0.8,0) 2(0.8,0)
  silkscreen extent -1.9,-0.8 1.2,0.8, body extent -0.85,-0.45 0.85,0.45, height 0.8
Wurth_60900213421 [mil] "Shunt, 2.54mm, Black"
  round 1 on Mech3: 0(0,0)
  body extent -98,-48 98,48, height 338
WURTH_61300311121 [mm] "Header, 2.54mm, 3x1, TH"
  rrect50% 1.65x1.65 hole 1.15: 1(-2.54,0)
  round 1.65 hole 1.15: 2(0,0) 3(2.54,0)
  body extent -3.81,-1.27 3.81,1.27, height 8.54
Wurth_61301421121 [mm] "Header, 2.54mm, 7x2, TH"
  rrect50% 1.65x1.65 hole 1.1: 1(-1.27,7.62)
  round 1.65 hole 1.1: 2(1.27,7.62) 3(-1.27,5.08) 4(1.27,5.08) 5(-1.27,2.54) 6(1.27,2.54) 7(-1.27,0) 8(1.27,0) 9(-1.27,-2.54) 10(1.27,-2.54) 11(-1.27,-5.08) 12(1.27,-5.08) 13(-1.27,-7.62) 14(1.27,-7.62)
  body extent -2.54,-8.89 2.54,8.89, height 8.55
XTAL_MS3V-T1R [mm] "Micro Crystal Switzerland recommended land pattern"
  rect 1.1x0.6 smd: 1(-2.775,0.45) 2(-2.775,-0.45)
  rect 2.4x1.5 smd: 3(2.775,0)
  silkscreen extent -1.9,-0.74 1.2,0.74, body extent -3.05,-0.74 3.65,0.74, height 1.42

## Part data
C1 C2 C56: library part CMP-0095152-1, "0.1 µF ±10% 100V Ceramic Capacitor X7R 0603 (1608 Metric)", Digikey Part Number=732-885012206120TR-ND, Manufacturer="Wurth Electronics", Mouser Part Number=710-885012206120, Operating Temperature Range="-55°C to +125°C", TempCo=15%, Temperature Characteristic=X7R, Tolerance_%=10%, ValueDisplayed=100nF
C3 C4 C5 C8 C23 C41 C57 C59: library part CMP-0097311-1, "1000 pF ±5% 100V Ceramic Capacitor C0G, NP0 0603 (1608 Metric)", Digikey Part Number=732-12187-1-ND, Manufacturer="Wurth Electronics", Mouser Part Number=710-885012006085, Operating Temperature Range="-55°C to +125°C", TempCo=30ppm/°C, Temperature Characteristic=NP0, Tolerance_%=5%, ValueDisplayed=1nF
C6 C15 C21 C25 C32 C33 C34 C36 C46 C50 C52 C53 C54: library part CMP-0006837-4, "CAP, CERM, 0.1 uF, 50 V, +/- 10%, X7R, 0603", Cap_Case=0603, Manufacturer="Wurth Elektronik", TempCo=X7R, Tolerance_%=10%, Value1=Unknown, Value2=50V, ValueDisplayed=0.1uF
C7: library part CMP-0078153-1, "CAP, CERM, 22 µF, 10 V,+/- 20%, X5R, 0805", Cap_Case=0805, Manufacturer="Wurth Elektronik", Supplier Part Number 1=732-7621-1-ND, TempCo=X5R, Tolerance_%=20%, Value2=10V, ValueDisplayed=22µF
C20: library part CMP-0097305-1, "4.7 µF ±20% 10V Ceramic Capacitor X5R 0603 (1608 Metric)", Digikey Part Number=732-7909-1-ND, Manufacturer="Wurth Electronics", Mouser Part Number=710-885012106012, Operating Temperature Range="-55°C to +85°C", TempCo=15%, Temperature Characteristic=X5R, Tolerance_%=20%, ValueDisplayed=4.7uF
C22 C24: library part CMP-0097306-1, "33 pF ±5% 50V Ceramic Capacitor C0G, NP0 0402 (1005 Metric)", Digikey Part Number=732-7472-1-ND, Manufacturer="Wurth Electronics", Mouser Part Number=710-885012005058, Operating Temperature Range="-55°C to +125°C", TempCo=30ppm/°C, Temperature Characteristic=NP0, Tolerance_%=5%, ValueDisplayed=33pF
C26 C27 C42 C43 C44 C45: library part CMP-0006215-2, "CAP, CERM, 10 pF, 50 V, +/- 5%, C0G/NP0, 0402", Cap_Case=0402, Manufacturer="Wurth Elektronik", Supplier Part Number 1=732-7469-1-ND, TempCo=C0G/NP0, Tolerance_%=5%, Value1=Unknown, Value2=50V, ValueDisplayed=10pF
C28 C30 C47: library part CMP-0006830-4, "CAP, CERM, 0.22 uF, 16 V, +/- 10%, X7R, 0603", Cap_Case=0603, Manufacturer="Wurth Elektronik", Supplier Part Number 1=710-885012206048, TempCo=X7R, Tolerance_%=10%, Value1=Unknown, Value2=16V, ValueDisplayed=0.22uF
C29 C49: library part CMP-0097299-1, "0.47 µF ±20% 10V Ceramic Capacitor X5R 0603 (1608 Metric)", Digikey Part Number=732-7905-1-ND, Manufacturer="Wurth Electronics", Mouser Part Number=710-885012106008, Operating Temperature Range="-55°C to +85°C", TempCo=15%, Temperature Characteristic=X5R, Tolerance_%=20%, ValueDisplayed=470nF
C31 C51: library part CMP-0097340-1, "Alum. Polymer Cap 10µF 10V 5.5mmV-Chip WCAP-PSLP Series Lifetime 2000h +105°C", Digikey Part Number=732-6401-1-ND, Leakage Current=300uA, Manufacturer="Wurth Electronics", Mouser Part Number=710-875105240001, Operating Temperature Range="-55°C to +105°C", Tolerance_%=20%, ValueDisplayed=10uF
C35 C40: library part CMP-0064924-2, "CAP, CERM, 1 uF, 10 V,+/- 20%, X5R, 0402", Cap_Case=0402, Manufacturer="Wurth Elektronik", Supplier Part Number 1=732-7489-1-ND, TempCo=X5R, Tolerance_%=20%, Value1=Unknown, Value2=10V, ValueDisplayed=1uF
C37 C39: library part CMP-0006227-2, "CAP, CERM, 0.01 uF, 16 V, +/- 10%, X7R, 0402", Cap_Case=0402, Manufacturer="Wurth Elektronik", Supplier Part Number 1=710-885012205031, TempCo=X7R, Tolerance_%=10%, Value1=Unknown, Value2=16V, ValueDisplayed=0.01uF
C38: library part CMP-0006825-5, "CAP, CERM, 2.2 uF, 16 V, +/- 20%, X5R, 0603", Cap_Case=0603, Manufacturer="Wurth Elektronik", Supplier Part Number 1=732-7915-1-ND, TempCo=X5R, Tolerance_%=20%, Value1=Unknown, Value2=16V, ValueDisplayed=2.2uF
C48: library part CMP-0090362-1, "0.1µF ±10% 10V Ceramic Capacitor X7R 0402 (1005 Metric)", Digikey Part Number=732-7513-1-ND, Manufacturer="Wurth Electronics", Mouser Part Number=710-885012205018, Operating Temperature Range="-55°C to +125°C", TempCo=15%, Temperature Characteristic=X7R, Tolerance_%=10%, ValueDisplayed=100000pF
C55: library part CMP-0081644-1, "CAP, AL, 100 µF, 50 V, +/- 20%, SMD", Cap_Case=8X10.5mm, Manufacturer="Wurth Elektronik", Supplier Part Number 1=732-8550-1-ND, Tolerance_%=20%, Value2=50V, ValueDisplayed=100µF
C58: library part CMP-0097312-1, "1 µF ±10% 100V Ceramic Capacitor X7R 1210 (3225 Metric)", Manufacturer="Wurth Electronics", Operating Temperature Range="-55°C to +125°C", TempCo=15%, Temperature Characteristic=X7R, Tolerance_%=10%, ValueDisplayed=1uF
C60: library part CMP-0097308-1, "100 pF ±5% 100V Ceramic Capacitor C0G, NP0 0402 (1005 Metric)", Digikey Part Number=732-12055-1-ND, Manufacturer="Wurth Electronics", Mouser Part Number=710-885012005080, Operating Temperature Range="-55°C to +125°C", TempCo=30ppm/°C, Temperature Characteristic=NP0, Tolerance_%=5%, ValueDisplayed=100pF
D1: library part CMP-0002947-3, "LED, Red, SMD", Color=Red, Manufacturer="Wurth Elektronik", Power_TotalModule=72mW, Value1=0.072W, Value2=2V
D2 D4 D5 D6 D8: library part CMP-0002894-2, "LED, Green, SMD", Color=green, Manufacturer="Wurth Elektronik", Value1=W, Value2=2V
D10: library part CMP-0002892-3, "LED, Yellow, SMD", Color=yellow, Manufacturer="Wurth Elektronik", Value1=W, Value2=2V
D11: library part CMP-0002893-1, "LED, Super Red, SMD", Color="super red", Manufacturer="Wurth Elektronik", Supplier Part Number 1=732-4979-1-ND, Value1=W, Value2=1.9V
F1: library part CMP-0077200-3, "Fuse, 30 A, 250 VAC, 100 VDC, SMD", Irating_A=30A, Manufacturer=Littelfuse, Supplier Part Number 1=F6439CT-ND
GND TP24: library part CMP-0055148-2, "Test Point, Multipurpose, Black, TH", Color=Black, Manufacturer="Keystone Electronics", Supplier Part Number 1=36-5011-ND
H2 H3 H4 H5: library part CMP-0003621-1, "Bumpon, Cylindrical, 0.312 X 0.200, Black", Manufacturer=3M, Supplier Part Number 1=SJ5746-0-ND
J1 J8: library part CMP-0093233-2, "2 Position Wire to Board Terminal Block Horizontal with Board 0.250\" (6.35mm) Through Hole", Current_A=32A, Digikey Part Number=732-691250610002-ND, Manufacturer="Wurth Electronics", Mouser Part Number=710-691250610002, Operating Temperature Range="-32°C to +120°C", Voltage_V=450V
J6: library part CMP-0054796-4, "Header, 2.54 mm, 3x1, Gold, TH", Manufacturer="Wurth Elektronik", Supplier Part Number 1=732-5316-ND
J9 J10: library part CMP-0086014-1, "Header, 2.54mm, 7x2, Gold, TH", Color=Black, Current_A=3A, Manufacturer="Wurth Elektronik", Voltage_V=250V
J11: library part CMP-1502-03253-1, "Micro USB 2.0 Type B Receptacle WR-COM, Horizontal, SMT, with Pads and Pegs", Contact Resistance=30mOhm, Manufacturer="Wurth Elektronik", Operating Temperature=-40to105degC, Rated Current=1A, Working Voltage=30VAC
L1 L2: library part CMP-0003184-2, "Ferrite Bead, 140 ohm @ 100 MHz, 0.55 A, 0603", Manufacturer="Wurth Elektronik", Supplier Part Number 1=732-4663-1-ND, Value1="0.2 ohm", Value2=0.55A, ValueDisplayed="140 ohm"
LBL1: library part CMP-0003625-1, "Thermal Transfer Printable Labels, 0.650\" W x 0.200\" H - 10,000 per roll", Manufacturer=Brady, Supplier Part Number 1=97C5133
Logo1: library part CMP-0074844-1
Logo2: library part CMP-0074838-1, "Texas Instrument Corporate Signature"
Logo3: library part CMP-0074847-1, "FCC_disclaimer"
Logo4: library part CMP-0074769-1
LOGO5: library part CMP-0074837-2, "IEC 61010-1 Hot Surface Warning", Manufacturer="Texas Instruments"
P1: library part CMP-1502-01114-1, "THT Vertical Pin Header WR-PHD, Pitch 2.54 mm, Dual Row, 26 pins", Contact Resistance=20mOhm, Manufacturer="Wurth Elektronik", Operating Temperature=-40to105degC, Rated Current=3A, Withstanding Voltage=500VAC, Working Voltage=250VAC
R1 R24 R39 R40 R41 R51 R52 R53: library part CMP-0025886-5, "RES, 10 k, 5%, 0.1 W, 0603", Manufacturer=Yageo, Power_W=100mW, Supplier Part Number 1=311-10KGRCT-ND, TempCo="100 ppm/C", Tolerance_%=5%, Value2=0.1W, Value_Code=10k0, ValueDisplayed=10k
R2: library part CMP-0022689-3, "RES, 1.50 k, 1%, 0.1 W, 0603", Manufacturer=Panasonic, Power_W=100mW, Supplier Part Number 1=P1.50KHCT-ND, TempCo="100 ppm/C", Tolerance_%=1%, Value2=0.1W, Value_Code=1k50, ValueDisplayed=1.50k
R3 R4 R62 R63 R68: library part CMP-0025697-4, "RES, 0, 5%, 0.1 W, AEC-Q200 Grade 0, 0603", Manufacturer=Vishay-Dale, PartNumber=CRCW06030000Z0EA, Power_W=100mW, Supplier Part Number 1=541-0.0GCT-ND, TempCo="200 ppm/C", Tolerance_%=5%, Value2=0.1W, Value_Code=0000, ValueDisplayed=0
R5 R8 R10: library part CMP-0027004-2, "RES, 0, 5%, 0.063 W, 0402", Manufacturer="Yageo America", Power_W=63mW, Supplier Part Number 1=311-0.0JRCT-ND, TempCo="200 ppm/C", Tolerance_%=5%, Value2=0.063W, Value_Code=0000, ValueDisplayed=0
R6 R7: library part CMP-0026232-2, "RES, 2.21 k, 1%, 0.063 W, AEC-Q200 Grade 0, 0402", Manufacturer=Vishay-Dale, Power_W=63mW, Supplier Part Number 1=541-2.21KLCT-ND, TempCo="100 ppm/C", Tolerance_%=1%, Value2=0.063W, Value_Code=2k21, ValueDisplayed=2.21k
R9 R37 R64 R65 R66 R67: library part CMP-0025963-3, "RES, 10.0, 1%, 0.063 W, AEC-Q200 Grade 0, 0402", Alternate Manufacturer="Wurth Electronics", Alternate PartNumber=560050310009, Manufacturer=Vishay-Dale, Power_W=63mW, Supplier Part Number 1=541-10.0LCT-ND, TempCo="100 ppm/C", Tolerance_%=1%, Value2=0.063W, Value_Code=10R0, ValueDisplayed=10.0
R11: library part CMP-0026962-3, "RES, 680, 5%, 0.063 W, AEC-Q200 Grade 0, 0402", Manufacturer=Vishay-Dale, Power_W=63mW, Supplier Part Number 1=541-680JCT-ND, TempCo="200 ppm/C", Tolerance_%=5%, Value2=0.063W, Value_Code=680R, ValueDisplayed=680
R12: library part CMP-0023504-3, "RES, 30.1 k, 0.1%, 0.1 W, 0603", Manufacturer="Susumu Co Ltd", Power_W=100mW, Supplier Part Number 1=RG16P30.1KBCT-ND, TempCo="25 ppm/C", Tolerance_%=0.1%, Value2=0.1W, Value_Code=30k1, ValueDisplayed=30.1k
R18 R19 R57: library part CMP-0026935-3, "RES, 47 k, 5%, 0.063 W, AEC-Q200 Grade 0, 0402", Manufacturer=Vishay-Dale, Power_W=63mW, Supplier Part Number 1=541-47KJCT-ND, TempCo="200 ppm/C", Tolerance_%=5%, Value2=0.063W, Value_Code=47k0, ValueDisplayed=47k
R35: library part CMP-0022458-4, "RES, 4.99 k, 1%, 0.1 W, AEC-Q200 Grade 0, 0603", Manufacturer=Vishay-Dale, Power_W=100mW, Supplier Part Number 1=541-4.99KHCT-ND, TempCo="100 ppm/C", Tolerance_%=1%, Value2=0.1W, Value_Code=4k99, ValueDisplayed=4.99k
R42 R59: library part CMP-0025930-5, "RES, 560, 5%, 0.1 W, 0603", Manufacturer=Yageo, Power_W=100mW, Supplier Part Number 1=311-560GRCT-ND, TempCo="100 ppm/C", Tolerance_%=5%, Value2=0.1W, Value_Code=560R, ValueDisplayed=560
R43 R45 R47 R48: library part CMP-0025785-4, "RES, 330, 5%, 0.1 W, AEC-Q200 Grade 0, 0603", Manufacturer=Vishay-Dale, Power_W=100mW, Supplier Part Number 1=541-330GCT-ND, TempCo="200 ppm/C", Tolerance_%=5%, Value2=0.1W, Value_Code=330R, ValueDisplayed=330
R55 R60: library part CMP-0026728-1, "RES, 220 k, 1%, 0.0625 W, 0402", Manufacturer="Yageo America", Power_W=62.5mW, Supplier Part Number 1=311-220KLRCT-ND, TempCo="100 ppm/C", Tolerance_%=1%, Value2=0.0625W, Value_Code=220k
R56: library part CMP-0026190-2, "RES, 240 k, 1%, 0.063 W, AEC-Q200 Grade 0, 0402", Manufacturer=Vishay-Dale, Power_W=63mW, Supplier Part Number 1=541-240KLCT-ND, TempCo="100 ppm/C", Tolerance_%=1%, Value2=0.063W, Value_Code=240k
